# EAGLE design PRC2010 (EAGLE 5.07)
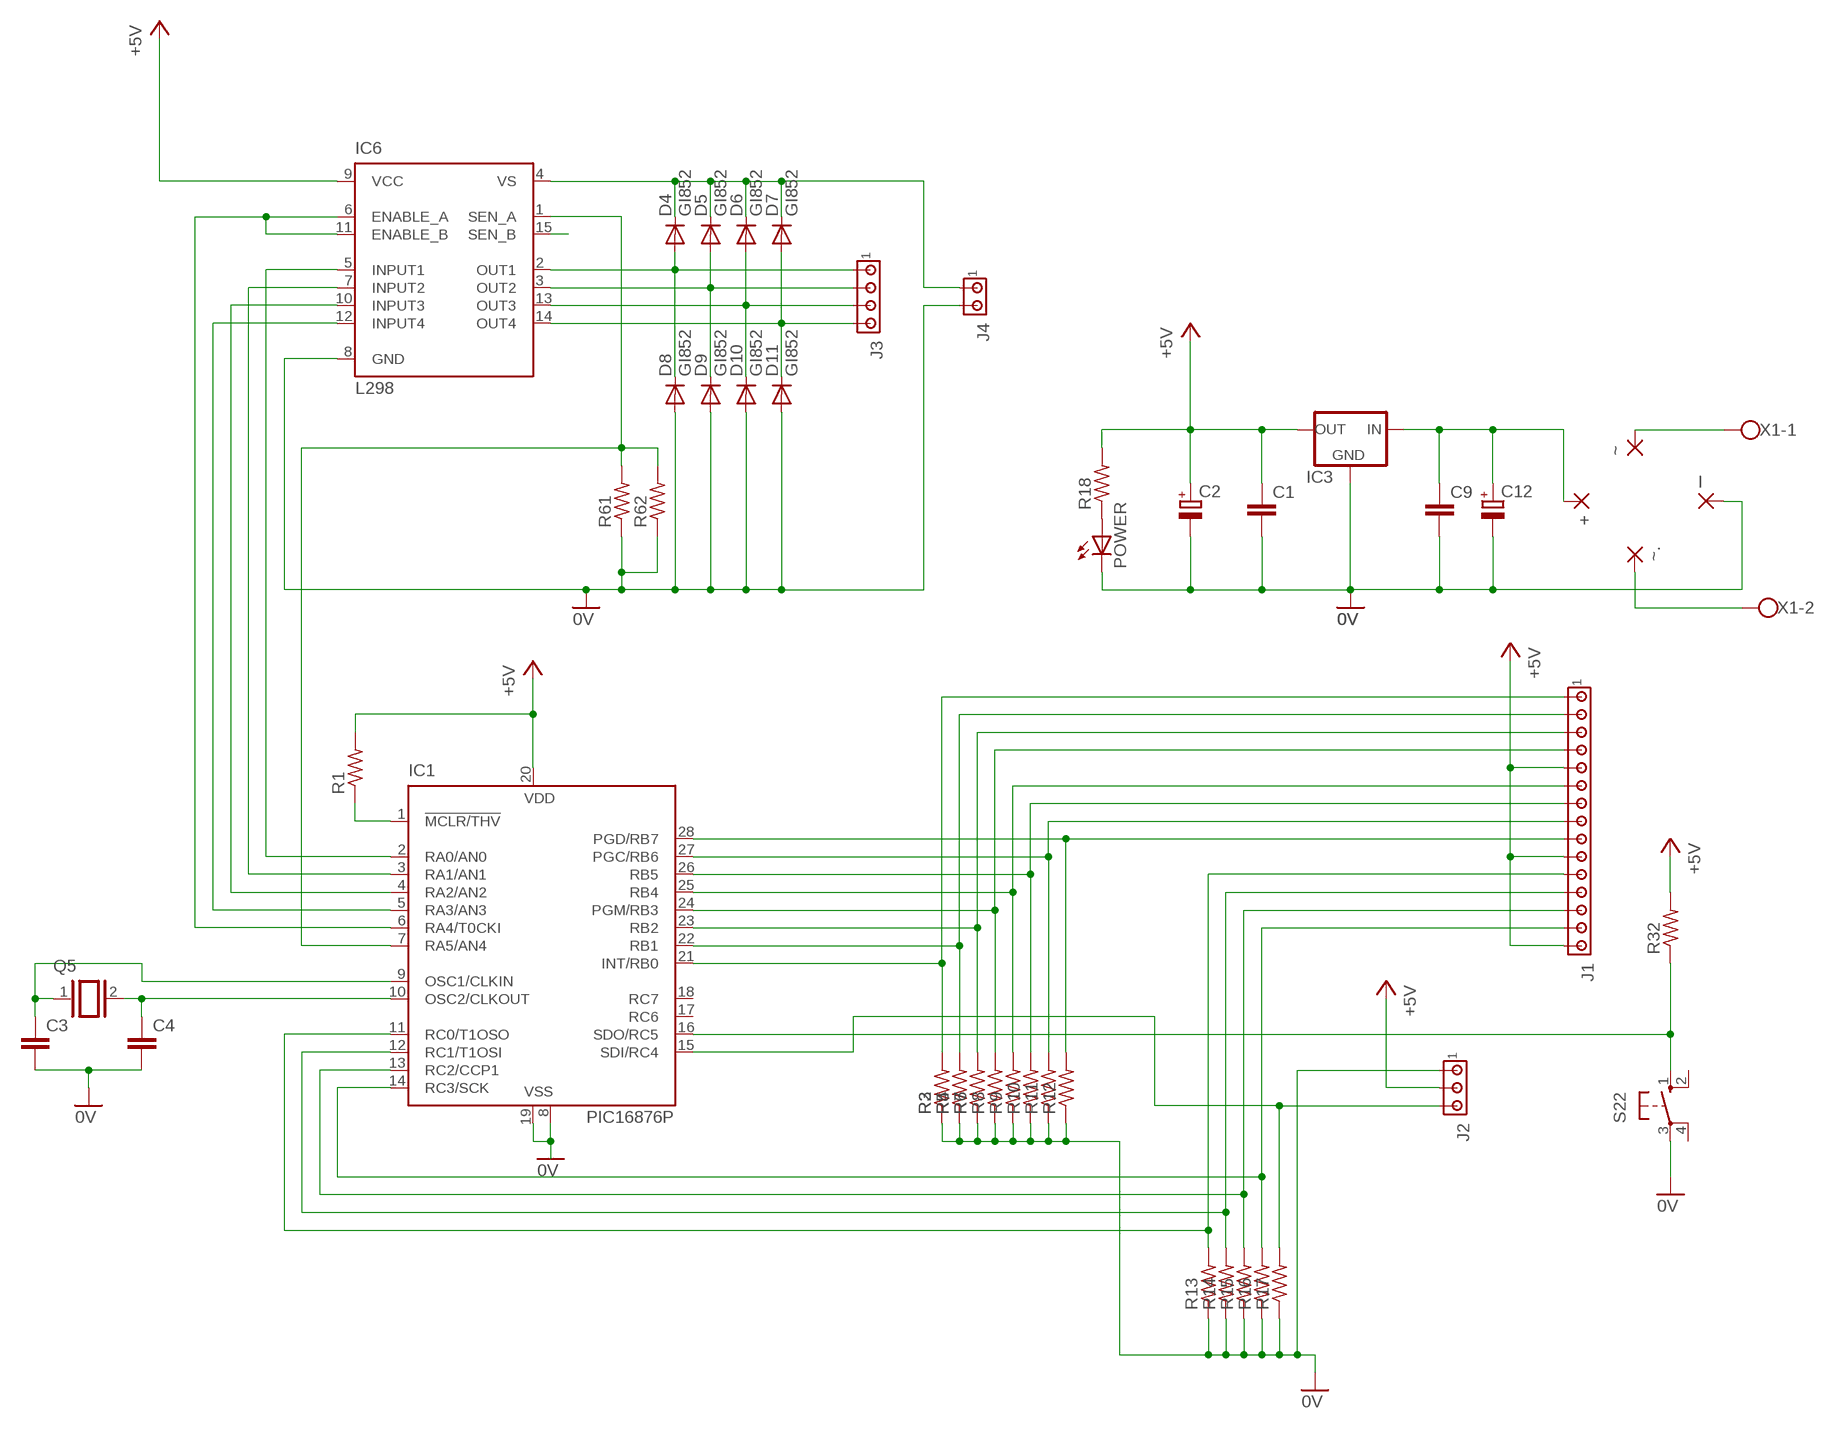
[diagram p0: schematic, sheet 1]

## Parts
+  1,6/0,9  [1,6/0,9]
C1  C-EU050-025X075  [C050-025X075]
C2  CPOL-EUE2.5-5  [E2,5-5]
C3  C2.5/2  [C2.5-2]
C4  C2.5/2  [C2.5-2]
C9  C-EU050-025X075  [C050-025X075]
C12  CPOL-EUE2.5-5  [E2,5-5]
D4  GI852  1N5400  [DO201-15]
D5  GI852  1N5400  [DO201-15]
D6  GI852  1N5400  [DO201-15]
D7  GI852  1N5400  [DO201-15]
D8  GI852  1N5400  [DO201-15]
D9  GI852  1N5400  [DO201-15]
D10  GI852  1N5400  [DO201-15]
D11  GI852  1N5400  [DO201-15]
I  1,6/0,9  [1,6/0,9]
IC1  PIC16876P  [DIL28-3]
IC3  78XXS  [78XXS]
IC6  L298  [MULTIWATT-15]
J1  MTA15-156  [1X15MTA]
J2  MTA03-100  [10X03MTA]
J3  MTA04-156  [1X4MTA]
J4  MTA02-156  [1X2MTA]
POWER  LED3MM  [LED3MM]
Q5  XTAL/S  [QS]
R1  R-US_0207/10  [0207/10]
R2  R-US_0207/10  [0207/10]
R3  R-US_0207/10  [0207/10]
R4  R-US_0207/10  [0207/10]
R5  R-US_0207/10  [0207/10]
R6  R-US_0207/10  [0207/10]
R7  R-US_0207/10  [0207/10]
R8  R-US_0207/10  [0207/10]
R9  R-US_0207/10  [0207/10]
R10  R-US_0207/10  [0207/10]
R11  R-US_0207/10  [0207/10]
R12  R-US_0207/10  [0207/10]
R13  R-US_0207/10  [0207/10]
R14  R-US_0207/10  [0207/10]
R15  R-US_0207/10  [0207/10]
R16  R-US_0207/10  [0207/10]
R17  R-US_0207/10  [0207/10]
R18  R-US_0207/10  [0207/10]
R32  R-US_0207/10  [0207/10]
R61  R-US_0207/10  [0207/10]
R62  R-US_0207/10  [0207/10]
S22  10-XX  [B3F-10XX]
X1  W237-102  [W237-102]
~  1,6/0,9  [1,6/0,9]
~.  1,6/0,9  [1,6/0,9]

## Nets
0V: C1.2 C2.- C3.2 C4.2 C9.2 C12.- D8.A D9.A D10.A D11.A I.1(P) IC1.8(VSS) IC1.19(VSS) IC3.GND IC6.8(GND) J2.1 J4.2 POWER.K(C) R2.1 R3.1 R4.1 R5.1 R6.1 R7.1 R8.1 R9.1 R10.1 R11.1 R12.1 R13.1 R14.1 R15.1 R16.1 R17.1 R61.1 R62.1 S22.3(P)
+5V: C1.1 C2.+ IC1.20(VDD) IC3.OUT IC6.9(VCC) J1.5 J1.10 J1.15 J2.2 R1.2 R18.2 R32.2
N$2: IC6.15(SEN_B)
N$3: IC1.1(!MCLR/THV) R1.1
N$4: IC1.16(SDO/RC5) R32.1 S22.1(S)
N$5: POWER.A R18.1
N$6: IC1.15(SDI/RC4) J2.3 R17.2
N$7: IC1.21(INT/RB0) J1.1 R2.2 R3.2
N$8: IC1.22(RB1) J1.2 R4.2 R5.2
N$9: IC1.11(RC0/T1OSO) J1.11 R13.2
N$10: IC1.24(PGM/RB3) J1.4 R8.2
N$11: IC1.25(RB4) J1.6 R9.2
N$12: IC1.26(RB5) J1.7 R10.2
N$13: IC1.27(PGC/RB6) J1.8 R11.2
N$14: IC1.28(PGD/RB7) J1.9 R12.2
N$16: IC1.12(RC1/T1OSI) J1.12 R14.2
N$17: IC1.13(RC2/CCP1) J1.13 R15.2
N$18: IC1.14(RC3/SCK) J1.14 R16.2
N$23: IC1.23(RB2) J1.3 R6.2 R7.2
N$26: C3.1 IC1.9(OSC1/CLKIN) Q5.1
N$45: C4.1 IC1.10(OSC2/CLKOUT) Q5.2
N$147: +.1(P) C9.1 C12.+ IC3.IN
N$179: IC1.6(RA4/T0CKI) IC6.6(ENABLE_A) IC6.11(ENABLE_B)
N$197: D4.A D8.C IC6.2(OUT1) J3.1
N$198: D5.A D9.C IC6.3(OUT2) J3.2
N$199: D6.A D10.C IC6.13(OUT3) J3.3
N$200: D7.A D11.C IC6.14(OUT4) J3.4
N$201: D4.C D5.C D6.C D7.C IC6.4(VS) J4.1
N$202: IC1.7(RA5/AN4) IC6.1(SEN_A) R61.2 R62.2
N$208: IC1.5(RA3/AN3) IC6.12(INPUT4)
N$209: IC1.4(RA2/AN2) IC6.10(INPUT3)
N$210: IC1.3(RA1/AN1) IC6.7(INPUT2)
N$211: IC1.2(RA0/AN0) IC6.5(INPUT1)
N$231: X1.1 ~.1(P)
N$232: X1.2 ~..1(P)
Unconnected: IC1.17(RC6) IC1.18(RC7) S22.2(S1) S22.4(P1)

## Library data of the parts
+ I ~ ~. = wirepad:1,6/0,9: THROUGH-HOLE PAD
C1 C9 = resistor:C-EU: CAPACITOR, European symbol
C2 C12 = resistor:CPOL-EU: POLARIZED CAPACITOR, European symbol
C3 C4 = capacitor-wima:C: CAPACITOR
D4-D11 = diode:1N5400: DIODE
IC1 = microchip:PIC16*876: MICROCONTROLLER flash type
IC3 = v-reg:78XXS: VOLTAGE REGULATOR
IC6 = st-microelectronics:L298: DUAL FULL-BRIDGE DRIVER
J1 = con-amp:MTA15-156: AMP connector
J2 = con-amp:MTA03-100: AMP connector
J3 = con-amp:MTA04-156: AMP connector
J4 = con-amp:MTA02-156: AMP connector
POWER = led:LED: LED
Q5 = special:XTAL/S: CRYSTAL
R1-R18 R32 R61 R62 = resistor:R-US_: RESISTOR, American symbol
S22 = switch-omron:10-XX: OMRON SWITCH
X1 = con-wago-500:W237-102: WAGO SCREW CLAMP

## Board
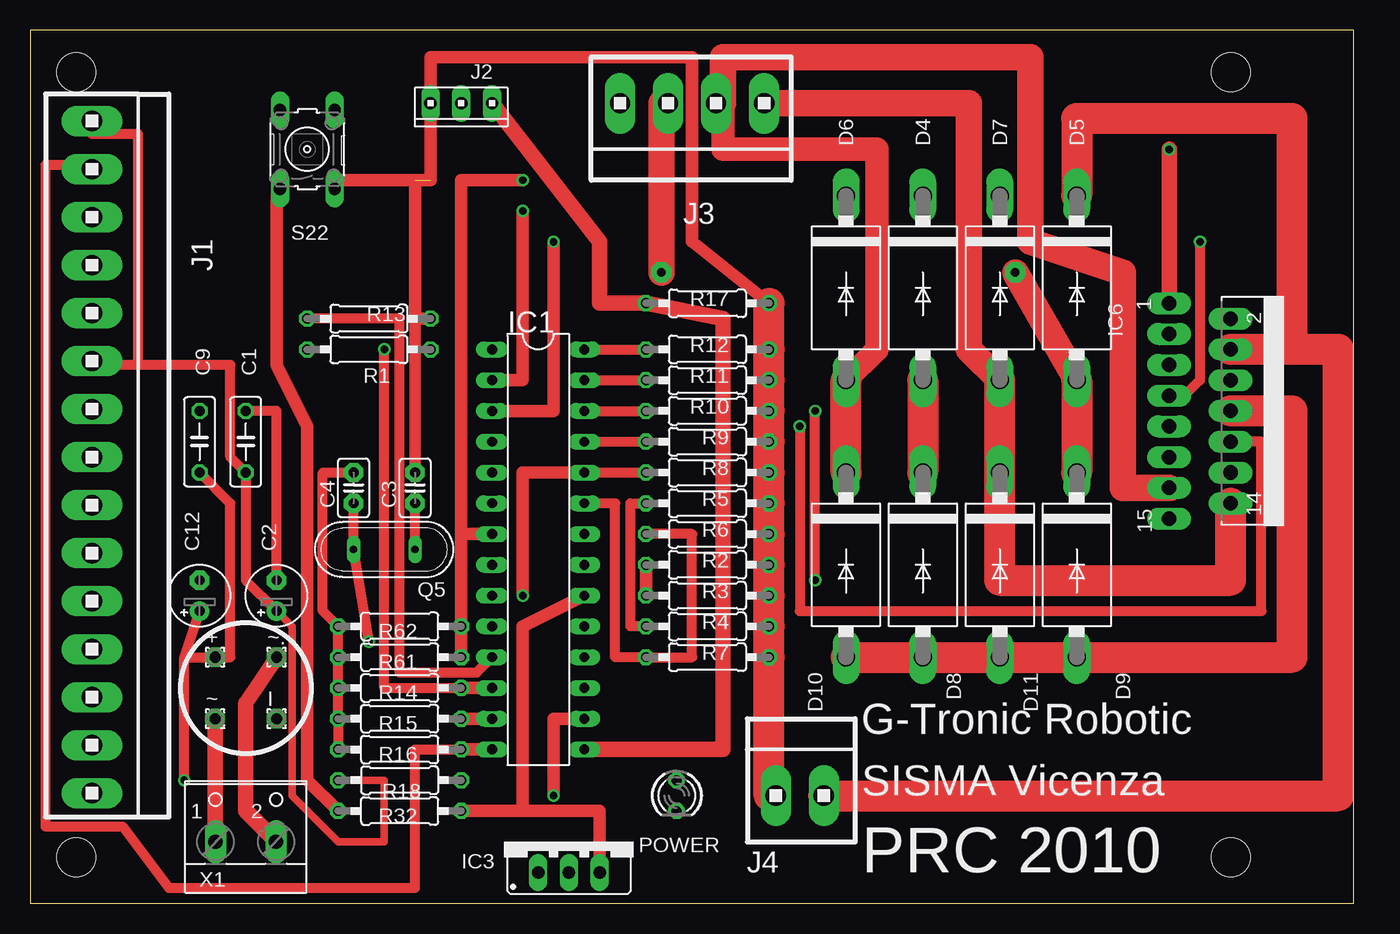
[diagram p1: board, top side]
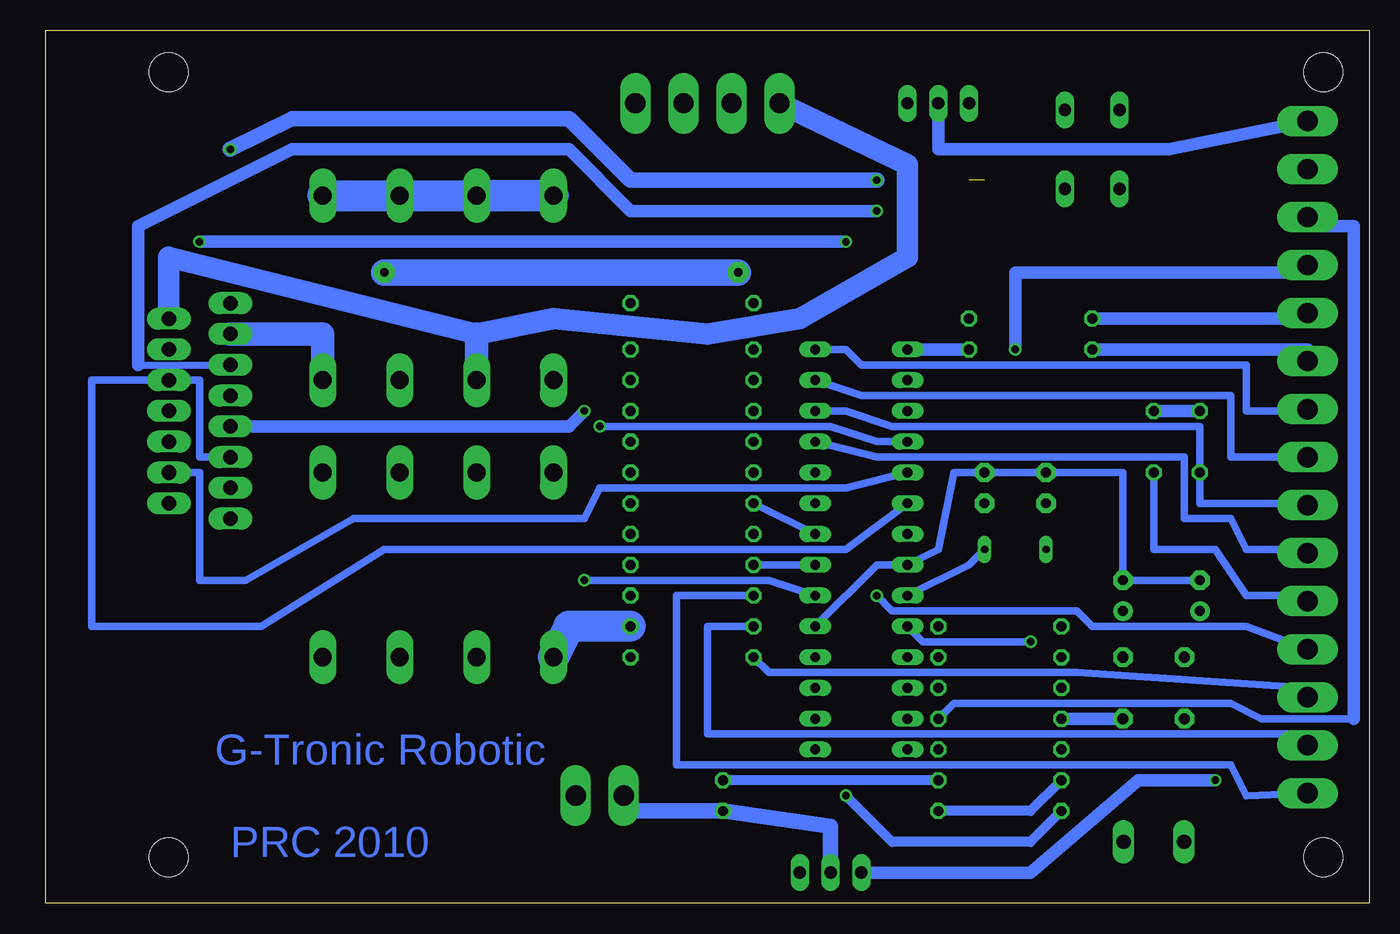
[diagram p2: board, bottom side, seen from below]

Size 109.2 x 72.06 mm. Coordinates in mm from the lower left corner, seen from the top.
Outline: 0,0 109.2,0 109.2,72.06 0,72.06 0,0
Copper layers (1*16): Top 0.035mm / dielectric 1.5mm / Bottom 0.035mm
Design rules "default": minimum track width 10mil, minimum drill 24mil, track to track 8mil, track to pad 8mil, pad to pad 8mil, via to via 8mil, smd to smd 8mil, copper to edge 40mil, drill to drill 8mil, minimum pad ring 10mil, minimum via ring 8mil, stop-mask expansion 4mil, vias tented up to drill 0mil, thermal gap 10mil
Holes 3.2 mm at 3.81,3.81 99.06,3.81 99.06,68.58 3.81,68.58

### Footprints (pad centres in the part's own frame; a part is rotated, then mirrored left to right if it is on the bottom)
1,6/0,9 = drill 0.914 pad 1.6 octagon: 1 0,0
C050-025X075 = drill 0.813 octagon: 1 -2.54,0; 2 2.54,0
E2,5-5 = drill 0.813 pad 1.6 round: + -1.27,0 | drill 0.813 pad 1.6 octagon: - 1.27,0
C2.5-2 = drill 0.813 pad 1.6 octagon: 1 -1.27,0; 2 1.27,0
DO201-15 = drill 1.499 long: A 7.62,0; C -7.62,0
DIL28-3 = drill 0.813 long: 1 -16.51,-3.81; 2 -13.97,-3.81; 3 -11.43,-3.81; 4 -8.89,-3.81; 5 -6.35,-3.81; 6 -3.81,-3.81; 7 -1.27,-3.81; 8 1.27,-3.81; 9 3.81,-3.81; 10 6.35,-3.81; 11 8.89,-3.81; 12 11.43,-3.81; 13 13.97,-3.81; 14 16.51,-3.81; 15 16.51,3.81; 16 13.97,3.81; 17 11.43,3.81; 18 8.89,3.81; 19 6.35,3.81; 20 3.81,3.81; 21 1.27,3.81; 22 -1.27,3.81; 23 -3.81,3.81; 24 -6.35,3.81; 25 -8.89,3.81; 26 -11.43,3.81; 27 -13.97,3.81; 28 -16.51,3.81
78XXS = drill 1.016 long: GND 0,-2.54; IN -2.54,-2.54; OUT 2.54,-2.54
MULTIWATT-15 = drill 1.2 long: 1 -8.89,-7.62; 2 -7.62,-2.54; 3 -6.35,-7.62; 4 -5.08,-2.54; 5 -3.81,-7.62; 6 -2.54,-2.54; 7 -1.27,-7.62; 8 0,-2.54; 9 1.27,-7.62; 10 2.54,-2.54; 11 3.81,-7.62; 12 5.08,-2.54; 13 6.35,-7.62; 14 7.62,-2.54; 15 8.89,-7.62
1X15MTA = drill 1.676 long: 1 27.737,0; 2 23.774,0; 3 19.812,0; 4 15.85,0; 5 11.887,0; 6 7.925,0; 7 3.962,0; 8 0,0; 9 -3.962,0; 10 -7.925,0; 11 -11.887,0; 12 -15.85,0; 13 -19.812,0; 14 -23.774,0; 15 -27.737,0
10X03MTA = drill 1.016 long: 1 2.54,0; 2 0,0; 3 -2.54,0
1X4MTA = drill 1.676 long: 1 5.944,0; 2 1.981,0; 3 -1.981,0; 4 -5.944,0
1X2MTA = drill 1.676 long: 1 1.981,0; 2 -1.981,0
LED3MM = drill 0.813 octagon: A -1.27,0; K 1.27,0
QS = drill 0.61 long: 1 -2.54,0; 2 2.54,0
0207/10 = drill 0.813 octagon: 1 -5.08,0; 2 5.08,0
B3F-10XX = drill 1.016 long: 1 -3.251,2.261; 2 3.251,2.261; 3 -3.251,-2.261; 4 3.251,-2.261
W237-102 = drill 1.194 long: 1 -2.5,-1.27; 2 2.5,-1.27

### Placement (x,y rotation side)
+  15.24,20.32 0 top
C1  17.78,38.1 90 top
C2  20.32,25.4 90 top
C3  31.75,34.29 90 top
C4  26.67,34.29 90 top
C9  13.97,38.1 90 top
C12  13.97,25.4 90 top
D4  73.66,50.8 270 top
D5  86.36,50.8 270 top
D6  67.31,50.8 270 top
D7  80.01,50.8 270 top
D8  73.66,27.94 270 top
D9  86.36,27.94 270 top
D10  67.31,27.94 270 top
D11  80.01,27.94 270 top
I  20.32,15.24 0 top
IC1  41.91,29.21 270 top
IC3  44.45,5.08 0 top
IC6  101.6,40.64 270 top
J1  5.08,36.83 270 top
J2  35.56,66.04 180 top
J3  54.61,66.04 180 top
J4  63.5,8.89 0 top
POWER  53.34,8.89 270 top
Q5  29.21,29.21 180 top
R1  27.94,45.72 180 top
R2  55.88,27.94 180 top
R3  55.88,25.4 180 top
R4  55.88,22.86 180 top
R5  55.88,33.02 180 top
R6  55.88,30.48 180 top
R7  55.88,20.32 180 top
R8  55.88,35.56 180 top
R9  55.88,38.1 180 top
R10  55.88,40.64 180 top
R11  55.88,43.18 180 top
R12  55.88,45.72 180 top
R13  27.94,48.26 180 top
R14  30.48,17.78 0 top
R15  30.48,15.24 0 top
R16  30.48,12.7 0 top
R17  55.88,49.53 180 top
R18  30.48,10.16 180 top
R32  30.48,7.62 0 top
R61  30.48,20.32 0 top
R62  30.48,22.86 0 top
S22  22.86,62.23 90 top
X1  17.78,6.35 0 top
~  15.24,15.24 0 top
~.  20.32,20.32 0 top

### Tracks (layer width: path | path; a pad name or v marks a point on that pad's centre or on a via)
0V  (1 unrouted)
  Top 0.254: J4.2 60.96,8.89
  Top 0.813: C1.2 20.32,40.64 C2.- | R16.1 R15.1 R14.1 R61.1 R62.1 24.13,24.13 24.13,35.56 C4.2
  Top 0.965: C3.2 31.75,48.26
  Top 1.016: S22.3 25.4,59.69 33.02,59.69 J2.1 33.02,69.85 54.61,69.85 54.61,54.61 R17.1 | R13.1 31.75,48.26 31.75,59.69
  Top 2.54: D10.A D8.A D11.A D9.A 104.14,20.32 104.14,40.64 IC6.8 | R17.1 R12.1 R11.1 R10.1 R9.1 R8.1 R5.1 R6.1 R2.1 R3.1 R4.1 R7.1 60.96,8.89
  Bottom 0.61: C12.- C2.- 20.32,35.56 C4.2 C3.2 34.29,35.56 35.56,29.21 IC1.8 40.64,27.94 IC1.19
  Bottom 1.016: C1.2 C9.2 | I.1 R15.1
  Bottom 1.27: J4.2 60.96,7.62 POWER.K 44.45,6.35 IC3.GND
  Bottom 2.54: D10.A 66.04,22.86 R4.1
+5V  (via drill 0.61)
  Top 0.254: 5.08,44.45 J1.10
  Top 0.61: C2.+ 21.59,22.86 21.59,8.89 25.4,5.08 29.21,5.08 29.21,10.16 R18.2
  Top 0.813: C2.+ 17.78,26.67 C1.1 16.51,36.83 16.51,44.45 8.89,44.45 | 8.89,44.45 5.08,44.45 | 8.89,44.45 8.89,63.5 5.08,63.5 J1.15 | v64.77,26.67 v64.77,40.64
  Top 1.016: IC1.20 40.64,22.86 40.64,7.62 | IC3.OUT 46.99,7.62 40.64,7.62 | R32.2 40.64,7.62
  Bottom 0.254: J1.5 5.08,25.4
  Bottom 0.61: C1.1 17.78,29.21 12.7,29.21 10.16,25.4 5.08,25.4 | v64.77,26.67 49.53,26.67 IC1.20
  Bottom 0.813: R18.2 27.94,7.62 R32.2
  Bottom 1.016: J2.2 35.56,62.23 16.51,62.23 J1.15 | R1.2 5.08,45.72 J1.10 | v64.77,40.64 66.04,39.37 IC6.9
N$3
  Bottom 1.016: R1.1 IC1.1
N$4  (via drill 0.61)
  Top 0.61: 20.32,58.42 S22.1
  Top 1.016: R32.1 22.86,10.16 22.86,39.37 20.32,44.45 20.32,58.42 | v43.18,8.89 43.18,15.24 IC1.16
  Bottom 0.813: v43.18,8.89 39.37,5.08 27.94,5.08 R32.1
N$5
  Bottom 0.813: R18.1 POWER.A
N$6
  Top 1.27: IC1.15 57.15,12.7 57.15,48.26 R17.2 46.99,49.53 46.99,54.61 J2.3
N$7
  Top 1.016: R3.2 R2.2
  Bottom 0.61: R2.2 IC1.21 | R3.2 57.15,25.4 57.15,11.43 11.43,11.43 10.16,8.89 J1.1
N$8
  Top 0.813: R4.2 49.53,22.86 49.53,33.02 R5.2
  Bottom 0.254: J1.2 5.08,13.97
  Bottom 0.61: R5.2 IC1.22 | 5.08,13.97 54.61,13.97 54.61,22.86 R4.2
N$9
  Top 0.813: IC1.11 36.83,19.05 30.48,19.05 30.48,48.26 R13.2
  Bottom 0.254: 5.08,48.26 J1.11
  Bottom 1.016: R13.2 5.08,48.26
N$10  (via drill 0.61)
  Top 0.813: IC1.24 R8.2
  Top 1.016: IC1.24 40.64,35.56 v40.64,25.4
  Bottom 0.61: v40.64,25.4 39.37,24.13 24.13,24.13 22.86,22.86 10.16,22.86 J1.4
N$11
  Top 0.813: IC1.25 R9.2
  Bottom 0.254: J1.6 5.08,29.21
  Bottom 0.61: IC1.25 40.64,36.83 15.24,36.83 15.24,31.75 11.43,31.75 10.16,29.21 5.08,29.21
N$12
  Top 0.813: IC1.26 R10.2
  Bottom 0.254: J1.7 5.08,33.02
  Bottom 0.61: IC1.26 43.18,40.64 39.37,39.37 13.97,39.37 13.97,33.02 5.08,33.02
N$13
  Top 0.813: IC1.27 R11.2
  Bottom 0.61: IC1.27 41.91,41.91 11.43,41.91 11.43,36.83 J1.8
N$14
  Top 0.813: IC1.28 R12.2
  Bottom 0.254: J1.9 5.08,40.64
  Bottom 0.61: IC1.28 43.18,45.72 41.91,44.45 10.16,44.45 10.16,40.64 5.08,40.64
N$16  (via drill 0.61)
  Top 0.813: R14.2 29.21,17.78 v29.21,45.72
  Top 1.016: R14.2 IC1.12
  Bottom 0.254: 5.08,52.07 J1.12
  Bottom 1.016: v29.21,45.72 29.21,52.07 5.08,52.07
N$17
  Top 1.016: R15.2 IC1.13
  Bottom 0.254: 5.08,55.88 J1.13
  Bottom 0.61: R15.2 34.29,16.51 11.43,16.51 8.89,15.24 1.27,15.24
  Bottom 1.016: 1.27,15.24 1.27,55.88 5.08,55.88
N$18
  Top 0.254: 5.08,60.96 J1.14
  Top 0.813: R16.2 31.75,12.7 31.75,1.27 25.4,1.27 11.43,1.27 7.62,6.35 1.27,6.35 1.27,60.96 5.08,60.96
  Top 1.016: R16.2 IC1.14
N$23
  Top 0.813: R6.2 54.61,30.48 54.61,20.32 R7.2 48.26,20.32 48.26,33.02 IC1.23
  Bottom 0.254: J1.3 5.08,17.78
  Bottom 0.61: 5.08,17.78 24.13,19.05 49.53,19.05 R7.2
N$26
  Top 0.813: Q5.1 C3.1
  Bottom 0.61: IC1.9 33.02,27.94 Q5.1
N$45  (via drill 0.61)
  Top 0.813: C4.1 Q5.2 v27.94,21.59
  Bottom 0.61: IC1.10 36.83,21.59 v27.94,21.59
N$147  (via drill 0.61)
  Top 0.813: C9.1 16.51,33.02 16.51,20.32 +.1 12.7,20.32 | v12.7,10.16 12.7,20.32 | 12.7,20.32 C12.+
  Bottom 1.016: IC3.IN 27.94,2.54 19.05,10.16 v12.7,10.16
N$179
  Bottom 0.61: IC1.6 43.18,29.21 81.28,29.21 91.44,22.86 105.41,22.86 105.41,43.18 IC6.6 96.52,43.18 96.52,36.83 IC6.11
N$197
  Top 2.54: D4.A D8.C
  Bottom 1.778: IC6.2 99.06,53.34 73.66,46.99 67.31,48.26 54.61,46.99 46.99,48.26 38.1,53.34 38.1,60.96 J3.1
  Bottom 1.93: 73.66,46.99 D4.A
N$198  (via drill 0.61 pad 0.61, 0.7 pad 1.68)
  Top 0.254: 52.07,66.04 J3.2
  Top 2.184: v52.07,52.07 52.07,66.04 | v81.28,52.07 D5.A
  Top 2.54: D5.A D9.C
  Bottom 1.93: IC6.3 86.36,46.99 D5.A
  Bottom 2.184: v52.07,52.07 v81.28,52.07
N$199
  Top 0.254: 57.15,66.04 J3.3
  Top 1.93: D6.A 69.85,45.72 69.85,62.23 57.15,62.23 57.15,66.04
  Top 2.184: IC6.13 90.17,34.29 90.17,52.07 82.55,54.61 82.55,69.85 57.15,69.85 57.15,66.04
  Top 2.54: D10.C D6.A
N$200
  Top 2.184: D7.A 77.47,45.72 77.47,66.04 J3.4
  Top 2.54: IC6.14 99.06,26.67 80.01,26.67 D11.C D7.A
N$201
  Top 0.254: 104.14,64.77 102.87,64.77 | J4.1 64.77,8.89
  Top 2.54: 104.14,45.72 IC6.4 | 104.14,45.72 104.14,64.77 86.36,64.77 D5.C | J4.1 107.95,8.89 107.95,45.72 104.14,45.72
  Bottom 2.54: D6.C D4.C D7.C D5.C D6.C
N$202  (via drill 0.61)
  Top 1.016: R61.2 R62.2 35.56,30.48 | 35.56,30.48 IC1.7 | v40.64,59.69 35.56,59.69 35.56,30.48
  Top 1.27: v93.98,62.23 IC6.1
  Bottom 1.27: v93.98,62.23 88.9,64.77 66.04,64.77 60.96,59.69 v40.64,59.69
N$208
  Bottom 0.61: IC1.5 43.18,34.29 63.5,34.29 64.77,31.75 83.82,31.75 92.71,26.67 96.52,26.67 96.52,35.56 IC6.12
N$209  (via drill 0.61)
  Top 0.813: v63.5,39.37 63.5,24.13 101.6,24.13 101.6,38.1 IC6.10
  Bottom 0.61: IC1.4 40.64,38.1 44.45,39.37 v63.5,39.37
N$210  (via drill 0.61)
  Top 0.813: v96.52,54.61 96.52,43.18 95.25,41.91 IC6.7
  Top 1.016: IC1.3 43.18,40.64 v43.18,54.61
  Bottom 1.016: v43.18,54.61 v96.52,54.61
N$211  (via drill 0.61)
  Top 1.016: IC1.2 40.64,43.18 v40.64,57.15
  Bottom 0.559: 101.6,44.45 IC6.5
  Bottom 1.016: v40.64,57.15 60.96,57.15 66.04,62.23 88.9,62.23 101.6,55.88 101.6,44.45
N$231
  Top 0.254: X1.1 15.24,5.08
  Top 1.27: 15.24,5.08 ~.1
N$232
  Top 0.254: X1.2 20.32,5.08
  Top 1.27: 20.32,5.08 17.78,7.62 17.78,16.51 ~..1

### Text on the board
Bottom: G-Tronic Robotic | PRC 2010
tNames: G-Tronic Robotic | SISMA Vicenza | PRC 2010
